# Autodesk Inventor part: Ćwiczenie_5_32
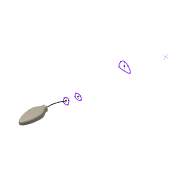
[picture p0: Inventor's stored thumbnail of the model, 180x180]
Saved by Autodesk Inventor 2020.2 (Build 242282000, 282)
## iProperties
Created: 2006-08
Part Number: Ćwiczenie_5_32
Document SubType Name: Modeling
Designer: F.Stasiak
Density: 1 g/cm^3
Material: Ogólny
Appearance: Jasnobeżowa
Manager: www.cadconsulting.pl
Company: Fabian Stasiak CAD Consulting
Author: F.Stasiak
Subject: Zbiór ćwiczeń. Autodesk Inventor 2020. Kurs podstawowy
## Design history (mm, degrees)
sketch "Szkic1"
  geometry: L1 (0, 3)-(0, -3); L2 (0, 0)-(-35, 0); L3 (5.525, 3)-(-5.525, 3); L4 (-5.525, -3)-(5.525, -3); A1 r 10.906 centre (0, 13.906) between (-4.096, 3.798) and (4.096, 3.798); A2 r 10.906 centre (0, -13.906) between (4.096, -3.798) and (-4.096, -3.798); 5 further points
  constraints: 8 end point, 5 midpoint, 3 horizontal, 2 centre point, 2 parallel, 2 point on circle, 2 symmetric about line, 1 coincident, 1 perpendicular, 1 vertical, 9 other
  dimensions: "d0" = 6 distance of L1.start L1.end; "d1" = 35 distance of L2.start L2.end; "d3" = 13 distance of point (-24.341, -6.5) point (-24.341, 6.5); "d4" = 12 distance of point (-6.988, -6) point (-6.988, 6)
extrude "Wyciągnięcie proste1" new body sketch "Szkic1" distance "d5" = 6; taper "d6" = 0 deg
sketch "Szkic2"
  geometry: L1 (0, 0)-(0, 6) reference; L2 (-4.528, 6)-(4.528, 6); A1 r 255.705 centre (0, -249.705) between (3.622, 5.974) and (-3.622, 5.974); 2 further points
  constraints: 2 end point, 2 horizontal, 2 midpoint, 1 centre point, 1 point on circle, 4 other
feature "PowWyciągnięciaProstego1" sketch "Szkic2" dims "d7" = 21.5, "d8" = 0
feature "Podział1"
fillet "Zaokrąglenie1" dims "d9" = 2, "d10" = 0.5
sketch "Szkic pomocniczy"
  geometry: L1 (0, 6)-(0, 0); L2 (17.626, 3)-(-17.626, 3); L3 (-151.15, -4.687)-(-177.127, -33.549); A1 r 323.149 centre (0, -320.149) between (14.087, 2.693) and (-14.087, 2.693); A2 r 84.066 centre (-101.653, -75.355) between (-152.881, -8.701) and (-173.316, -31.407); 6 further points
  constraints: 6 end point, 5 midpoint, 2 centre point, 2 horizontal, 2 point on circle, 1 vertical, 14 other
node "Płaszczyzna konstrukcyjna1"
node "Płaszczyzna konstrukcyjna2"
node "Płaszczyzna konstrukcyjna3"
node "Płaszczyzna konstrukcyjna4"
sketch "Szkic4"
  geometry: L1 (0, 3.5)-(0, -3.5); 6 further points
  constraints: 2 end point, 2 symmetric about line, 1 coincident, 1 midpoint, 1 vertical, 6 other
  dimensions: "d11" = 7 distance of L1.start L1.end; "d95" = 6.5 distance of point (-3.25, -2.521) point (3.25, -2.521)
sketch "Szkic5"
  geometry: L1 (3.14, 3)-(-3.14, 3); L2 (-29.543, 0.379)-(-27.167, -6.205) reference; L3 (-25.502, -1.883)-(-31.208, -3.943); A1 r 273.265 centre (0, -270.265) between (2.512, 2.988) and (-2.512, 2.988); 6 further points
  constraints: 4 end point, 4 midpoint, 2 horizontal, 1 centre point, 1 perpendicular, 1 point on circle, 9 other
sketch "Szkic6"
  geometry: L1 (0, 3.5)-(0, -3.5); 6 further points
  constraints: 2 end point, 2 symmetric about line, 1 coincident, 1 midpoint, 1 vertical, 6 other
  dimensions: "d23" = 7 distance of L1.start L1.end; "d24" = 8 distance of point (-4, -1.96) point (4, -1.96); "d25" = 6 distance of point (-3, 2.481) point (3, 2.481)
sketch "Szkic7"
  geometry: L1 (0, 6)-(0, -6); 6 further points
  constraints: 2 end point, 2 symmetric about line, 1 coincident, 1 midpoint, 1 vertical, 6 other
  dimensions: "d26" = 12 distance of L1.start L1.end; "d27" = 15 distance of point (-7.5, -4.479) point (7.5, -4.479)
sketch "Szkic8"
  geometry: 1 further point
node "Bryła1"
node "Korpusy bryłowe"
node "Korpusy powierzchniowe"
body "Srf1"
